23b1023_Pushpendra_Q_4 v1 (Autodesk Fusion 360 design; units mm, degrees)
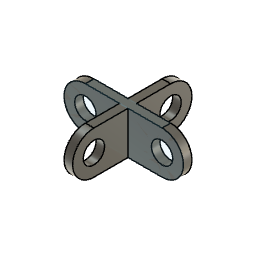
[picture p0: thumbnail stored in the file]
sketch "Sketch1" plane through (0, 0, 0) normal (0, 1, 0) x axis (1, 0, 0)
  line L1 (40, -40) -> (-50, -40)
  line L2 (40, 10) -> (-50, 10)
  line L3 (-10, 10) -> (-10, -40)
  line L4 (0, 10) -> (0, -40)
  arc A1 centre (40, -15) radius 25 clockwise from (40, 10) to (40, -40)
  arc A2 centre (-50, -15) radius 25 clockwise from (-50, -40) to (-50, 10)
  circle C1 centre (-50, -15) radius 12.5
  circle C2 centre (40, -15) radius 12.5
  point P2 (-10, -40)
  point P3 (-10, 10)
  point P4 (0, -40)
  point P5 (0, 10)
  point P11 (-50, -15)
  point P8 (40, -15)
  point P1 (0, 0)
  horizontal L1
  horizontal L2
  coincident L1 P2
  perpendicular L1 L3
  coincident L2 P3
  coincident L1 P4
  perpendicular L1 L4
  coincident L2 P5
  concentric A2 C1
  concentric A1 C2
  dimension "d6" distance L3 L4 = 10
  dimension "d8" radius A2 = 25
  dimension "d9" distance L3 P11 = 40
  dimension "d10" distance L4 P8 = 40
  dimension "d11" diameter C1 = 25
  dimension "d12" diameter C2 = 25
  dimension "d13" distance P1 L3 = 10
  dimension "d14" distance P1 L1 = 40
  dimension "d15" radius A1 = 25
extrude "Extrude1" new body sketch "Sketch1" along normal blind 10
sketch "Sketch2" plane through (0, 0, 0) normal (0, 0, 1) x axis (1, 0, 0)
sketch "Sketch3" plane through (0, 0, 0) normal (1, 0, 0) x axis (0, 1, 0)
sketch "Sketch4" plane through (0, 0, 0) normal (0, 0, 1) x axis (1, 0, 0)
sketch "Sketch5" plane through (0, 0, 0) normal (1, 0, 0) x axis (0, 1, 0)
sketch "Sketch6" plane through (0, 0, 40) normal (0, 0, 1) x axis (-1, 0, 0)
  line L1 (-40, 0) -> (50, 0)
  line L2 (-40, -10) -> (-40, 0)
  line L3 (50, -10) -> (-40, -10)
  line L4 (50, 0) -> (50, -10)
sketch "Sketch7" plane through (0, 0, 0) normal (0, -1, 0) x axis (1, 0, 0)
  line L1 (40, -10) -> (-50, -10)
  line L2 (-50, 40) -> (40, 40)
  circle C1 centre (40, 15) radius 12.5
  circle C2 centre (-50, 15) radius 12.5
  arc A1 centre (-50, 15) radius 25 clockwise from (-50, -10) to (-50, 40)
  arc A2 centre (40, 15) radius 25 clockwise from (40, 40) to (40, -10)
sketch "Sketch8" plane through (0, 0, 0) normal (1, 0, 0) x axis (0, 1, 0)
sketch "Sketch9" plane through (0, 0, 0) normal (1, 0, 0) x axis (0, 1, 0)
  line L1 (-40, 40) -> (50, 40)
  line L2 (-40, -10) -> (50, -10)
  arc A1 centre (50, 15) radius 25 clockwise from (50, 40) to (50, -10)
  arc A2 centre (-40, 15) radius 25 clockwise from (-40, -10) to (-40, 40)
  circle C1 centre (50, 15) radius 12.5
  circle C2 centre (-40, 15) radius 12.5
  point P2 (0, 0)
  point P5 (50, 15)
  point P9 (0, 0)
  point P8 (-40, 15)
  horizontal L1
  horizontal L2
  tangent L1 A2
  tangent L2 A2
  concentric A1 C1
  concentric A2 C2
  dimension "d18" distance L2 P2 = 10
  dimension "d19" distance L1 L2 = 50
  dimension "d20" radius A1 = 25
  dimension "d21" distance P5 P9 = 50
  dimension "d22" distance P2 P8 = 40
  dimension "d23" diameter C1 = 25
  dimension "d24" diameter C2 = 25
extrude "Extrude2" add sketch "Sketch9" against normal blind 10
